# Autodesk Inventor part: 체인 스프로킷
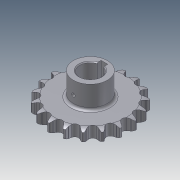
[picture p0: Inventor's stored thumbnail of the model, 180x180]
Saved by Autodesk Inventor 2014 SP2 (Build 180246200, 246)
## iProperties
Created: 2014-07
Part Number: 체인 스프로킷
Material: 강
Document SubType Name: Modeling
Designer: KYOUNG IL JANG
Density: 7.85 g/cm^3
Appearance: 강철
Mass: 738.603 g
Surface Area: 236.854 cm^2
Volume: 94.0896 cm^3
CustomPartVersion: 1
Company: 한국ATC센터
Author: KYOUNG IL JANG
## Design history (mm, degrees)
sketch "이론적 톱니 프로파일"
  geometry: L1 (0, 0)-(0, 45.567); L2 (0, 0)-(14.795, 43.098); L3 (0, 45.567)-(14.795, 43.098); L4 (0, 45.567)-(5.661, 50.015); L5 (5.661, 50.015)-(-5.141, 45.406); L6 (-12.428, 43.493)-(-5.573, 46.417); L7 (-5.141, 45.406)-(-5.573, 46.417); L8 (5.573, 46.417)-(5.141, 45.406); L9 (0, 0)-(8.138, 48.771); A1 r 45.567 centre (0, 0) between (0, 45.567) and (14.795, 43.098); A2 r 49.445 centre (0, 0) between (7.302, 48.903) and (-7.302, 48.903); A3 r 4.545 centre (0, 45.567) between (-3.574, 42.758) and (3.574, 42.758); A4 r 7.453 centre (12.428, 43.493) between (7.302, 48.903) and (5.573, 46.417); A5 r 7.453 centre (-12.428, 43.493) between (-5.573, 46.417) and (-7.302, 48.903); A6 r 11.745 centre (5.661, 50.015) between (-5.141, 45.406) and (-3.574, 42.758); A7 r 11.745 centre (-5.661, 50.015) between (3.574, 42.758) and (5.141, 45.406); 2 further points
  constraints: 18 end point, 15 point on circle, 7 centre point, 3 coincident, 3 point on line, 3 symmetric about line, 3 tangent, 1 equal radius, 1 midpoint, 1 parallel, 1 vertical, 1 other
  dimensions: "d0" = 91.13301 diameter of A1 (computed from da_p, da_z); "d2" = 18.9474 deg angle of L2 L1 (computed from da_z); "d3" = 4.545 radius of A3 (= 0.5 x da_Dr + da_SC); "d10" = 128.158 deg angle of L4 L1 (computed from da_z); "d11" = 15.0526 deg angle of L5 L4 (computed from da_z); "d12" = 7.2 distance of L3.start L4.end (= 0.8 x da_Dr); "d13" = 11.745 distance of L4.end L5.end (= 1.3 x da_Dr + da_SC); "d14" = 12.6 distance of A4.centre L1.end (= 1.4 x da_Dr); "d23" = 4.5 distance from line of L9.end L3 (= da_Ha)
sketch "톱니 프로파일"
  geometry: L1 (0, 0)-(0, 45.567); L2 (0, 45.567)-(4.203, 43.837); L3 (0, 45.567)-(-4.203, 43.837); A1 r 4.545 centre (0, 45.567) between (-4.203, 43.837) and (4.203, 43.837); A2 r 22.68 centre (25.176, 35.206) between (7.12, 48.93) and (4.203, 43.837); A3 r 22.68 centre (-25.176, 35.206) between (-4.203, 43.837) and (-7.12, 48.93); A4 r 49.445 centre (0, 0) between (-7.12, 48.93) and (7.12, 48.93) reference; 1 further point
  constraints: 9 point on circle, 6 end point, 3 centre point, 2 tangent, 1 coincident, 1 equal radius, 1 vertical, 1 other
  dimensions: "d44" = 135.263 deg angle of L3 L2 (= da_Alfa); "d45" = 22.68 radius of A2 (= da_Re); "d46" = 4.545 radius of A1 (= da_Ri)
sketch "단면 프로파일"
  geometry: L1 (49.445, 0)-(-49.445, 0) reference; L2 (33.265, 6.65)-(-33.265, 6.65); L3 (-33.265, 6.65)-(-33.265, -6.65); L4 (-33.265, -6.65)-(33.265, -6.65); L5 (33.265, -6.65)-(33.265, 6.65); L6 (33.265, 6.65)-(49.445, 6.65); L7 (49.445, 6.65)-(49.445, -6.65); L8 (49.445, -6.65)-(33.265, -6.65); L9 (33.265, -6.65)-(33.265, 6.65); L10 (42.183, 6.65)-(0, 6.65); L11 (0, 6.65)-(0, -6.65); L12 (0, -6.65)-(42.183, -6.65); L13 (0, 6.65)-(0, -6.65); L14 (49.445, 4.775)-(49.445, -4.775); A1 r 15 centre (42.183, -8.35) between (49.445, 4.775) and (42.183, 6.65); A2 r 15 centre (42.183, 8.35) between (42.183, -6.65) and (49.445, -4.775); 2 further points
  constraints: 26 end point, 7 midpoint, 5 perpendicular, 4 parallel, 4 point on circle, 3 point on line, 3 symmetric about line, 2 centre point, 2 horizontal, 2 tangent, 1 collinear, 1 other
  dimensions: "d30" = 13.3 distance between parallel lines of L8 L6 (= da_Bf); "d31" = 66.53007 distance between parallel lines of L3 L5 (= da_Ds); "d32" = 13.3 distance between parallel lines of L4 L2 (= da_Bs); "d33" = 1.875 distance from line of L14.start L6 (= da_Ba); "d34" = 15 radius of A1 (= da_Rx); "d43" = 6.65 distance between parallel lines of L4 L1 (computed from da_k, da_pt, da_Bs)
revolve "슈라우드" stored, may be unused: angle "d36" = 90 deg
revolve "스트랜드" stored, may be unused: angle "d37" = 90 deg
extrude "이론적 톱니" cut sketch "이론적 톱니 프로파일" stored distance "d18" = 10; taper "d19" = 0 deg; dims "d49" = 0, "form_type" = 0 [user parameter]
extrude "톱니" cut sketch "톱니 프로파일" stored distance "d47" = 10; taper "d48" = 0 deg; dims "d50" = 10, "form_type" = 0 [user parameter]
node "타이밍 평면"
node "작업 평면3"
sketch "스케치5"
  geometry: C1 r 20 at (0, -45.567); 1 further point
  constraints: 1 centre point, 1 coincident
  dimensions: "d52" = 40 diameter of C1
extrude "돌출4" join sketch "스케치5" stored distance "d53" = 10; taper "d54" = 0 deg
sketch "스케치6"
  geometry: L1 (4, 11.843)-(4, 16.5); L2 (4, 16.5)-(-4, 16.5); L3 (-4, 16.5)-(-4, 11.843); A1 r 12.5 centre (0, 0) between (4, 11.843) and (-4, 11.843); 1 further point
  constraints: 6 end point, 2 parallel, 2 point on circle, 1 centre point, 1 coincident, 1 perpendicular, 1 vertical
  dimensions: "d55" = 25 diameter of A1; "d56" = 29 dimension on A1 L2 (computed from d55); "d57" = 8 distance of L1.end L2.end
extrude "돌출5" cut sketch "스케치6" stored distance "d58" = 10; taper "d59" = 0 deg
fillet "모깎기2" dims "d60" = 3
chamfer "모따기1" distance "d61" = 1; stored, may be unused: second distance "d62" = 2, angle "d63" = 45 deg
node "작업 평면4"
sketch "스케치7"
  geometry: L1 (-13.5, -13.3)-(13.5, -13.3) reference; 4 further points
  constraints: 1 vertical alignment
  dimensions: "d65" = 25 distance from line of point (0, 11.7) L1
hole "구멍1" sketch "스케치7" at (0, 11.7) diameter "d66" = 4.134; stored, may be unused: countersink angle "d70" = 90 deg, drill point angle "d72" = 118 deg; dims "d67" = 6, "d68" = 4, "d69" = 2, "d71" = 8
body "Solid1"
pattern_linear "스트랜드 패턴" dims "d40" = 24 (= da_pt)
pattern_circular "톱니 패턴" dims angle "d21" = 360 deg
other parameters: "da_p" = 15 [user parameter; used in 1 equation term], "da_Dr" = 9 [user parameter; used in 4 equation terms], "da_SC" = 0.045 [user parameter; used in 2 equation terms], "da_Ha" = 4.5 [user parameter; used in 1 equation term], "da_pt" = 24 [user parameter; used in 2 equation terms], "da_Bf" = 13.3 [user parameter; used in 1 equation term], "d28" = 0, "d29" = 0, "da_Ba" = 1.875 [user parameter; used in 1 equation term], "da_Rx" = 15 [user parameter; used in 1 equation term], "da_Ra" = 0.6 [user parameter], "da_Bs" = 13.3 [user parameter; used in 2 equation terms], "da_Ds" = 66.53007 [user parameter; used in 1 equation term], "d42" = 0, "da_Re" = 22.68 [user parameter; used in 1 equation term], "da_Ri" = 4.545 [user parameter; used in 1 equation term], "da_Alfa" = 135.263 deg [user parameter; used in 1 equation term]
